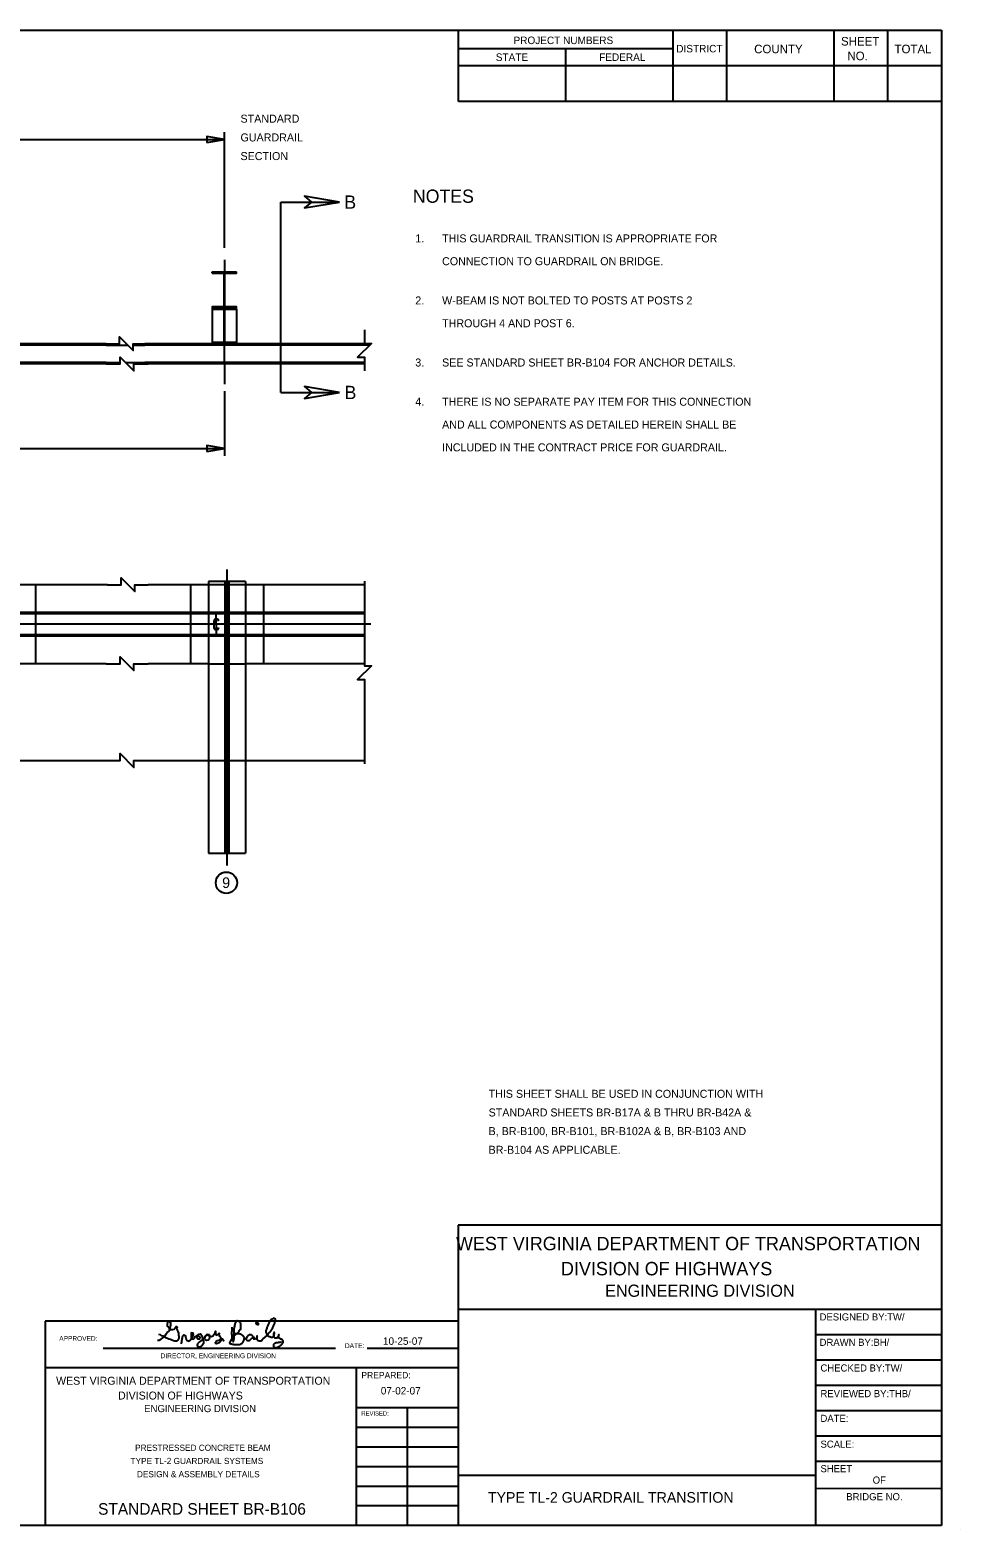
# Model space of a CAD drawing. Extents: x 809.7 to 842.4, y -901 to -880.3.
# Drawn here: x 829.59 to 842.35, y -900.96 to -880.4 of the extents above; entities that cross this region are included whole.
import ezdxf

# ---------------------------------------------------------------- set-up
doc = ezdxf.new("R2010")
doc.units = 0
for name, color, linetype in [('CONSTRUCTION LINE', 7, 'Continuous'), ('CURBLINE', 7, 'Continuous'), ('Default', 7, 'Continuous'), ('DIMENSION LINE', 7, 'Continuous'), ('EDGE OF PAVEMENT', 7, 'Continuous'), ('HIDDEN LINE', 7, 'Continuous'), ('Level 1', 7, 'Continuous'), ('OBJECT LINE', 7, 'Continuous'), ('REBAR', 7, 'Continuous'), ('STRUCTURES CENTERLINE', 7, 'Continuous'), ('STRUCTURES TEXT', 7, 'Continuous'), ('Text', 7, 'Continuous')]:
    doc.layers.add(name, color=color, linetype=linetype)

msp = doc.modelspace()

# ---------------------------------------------------------------- linework, layer by layer
at = {"layer": 'CONSTRUCTION LINE'}
msp.add_line((842.355, -900.957), (842.355, -900.957), dxfattribs=at)
msp.add_line((842.355, -900.957), (842.355, -900.957), dxfattribs=at)
at = {"layer": 'CURBLINE'}
msp.add_line((842.094, -896.791), (835.47, -896.79), dxfattribs=at)
msp.add_line((842.094, -896.791), (835.47, -896.79), dxfattribs=at)
at = {"layer": 'Default'}
for p, q in [((830.598, -898.475), (833.786, -898.475)), ((834.222, -898.475), (835.46, -898.475))]:
    msp.add_line(p, q, dxfattribs=at)
at = {"layer": 'DIMENSION LINE'}
for p, q in [((832.26, -883.385), (832.26, -881.801)), ((826.01, -881.9), (832.26, -881.9)), ((832.26, -885.352), (832.26, -886.236)), ((819.76, -886.137), (832.26, -886.137)), ((832.116, -888.508), (832.116, -888.591))]:
    msp.add_line(p, q, dxfattribs=at)
for centre, start, end in [((832.15, -888.508), 360, 180), ((832.15, -888.591), 180, 0)]:
    msp.add_arc(centre, 0.0339, start, end, dxfattribs=at)
at = {"layer": 'EDGE OF PAVEMENT'}
for points in [[(832.02, -881.94), (832.26, -881.9), (832.02, -881.86)], [(832.02, -886.177), (832.26, -886.137), (832.02, -886.096)]]:
    msp.add_lwpolyline(points, close=True, dxfattribs=at)
msp.add_lwpolyline([(832.26, -886.137), (832.205, -886.137)], dxfattribs=at)
msp.add_circle((832.289, -892.093), 0.146, dxfattribs=at)
at = {"layer": 'HIDDEN LINE'}
for p, q in [((830.637, -884.72), (830.935, -884.72)), ((831.009, -884.72), (831.169, -884.72)), ((832.26, -884.978), (832.26, -884.701)), ((830.637, -884.958), (816.236, -884.958)), ((830.637, -884.957), (830.832, -884.957)), ((830.904, -884.957), (831.169, -884.957)), ((834.183, -884.957), (831.169, -884.957)), ((832.549, -887.964), (832.042, -887.964)), ((832.042, -887.964), (832.042, -890.417)), ((832.549, -887.964), (832.042, -887.964)), ((832.042, -887.964), (832.042, -890.417)), ((832.549, -887.964), (832.042, -887.964)), ((832.042, -887.964), (832.042, -890.417)), ((832.549, -887.964), (832.042, -887.964)), ((832.042, -887.964), (832.042, -890.417)), ((832.549, -887.964), (832.042, -887.964)), ((832.042, -887.964), (832.042, -890.417)), ((832.549, -887.964), (832.042, -887.964)), ((832.042, -887.964), (832.042, -890.417)), ((832.549, -887.964), (832.042, -887.964)), ((832.042, -887.964), (832.042, -890.417)), ((832.549, -887.964), (832.042, -887.964)), ((832.042, -887.964), (832.042, -890.417)), ((832.549, -887.964), (832.042, -887.964)), ((832.042, -887.964), (832.042, -890.417)), ((832.549, -887.964), (832.042, -887.964)), ((832.042, -887.964), (832.042, -890.417)), ((832.549, -887.964), (832.042, -887.964)), ((832.042, -887.964), (832.042, -890.417)), ((832.549, -887.964), (832.042, -887.964)), ((832.042, -887.964), (832.042, -890.417)), ((832.549, -887.964), (832.042, -887.964)), ((832.042, -887.964), (832.042, -890.417)), ((832.549, -887.964), (832.042, -887.964)), ((832.042, -887.964), (832.042, -890.417)), ((832.549, -887.964), (832.042, -887.964)), ((832.042, -887.964), (832.042, -890.417)), ((832.549, -887.964), (832.042, -887.964)), ((832.042, -887.964), (832.042, -890.417)), ((832.269, -887.964), (832.269, -891.69)), ((832.322, -887.964), (832.322, -891.69)), ((832.549, -887.964), (832.549, -890.417)), ((832.549, -887.964), (832.549, -890.417)), ((832.549, -887.964), (832.549, -890.417)), ((832.549, -887.964), (832.549, -890.417)), ((832.549, -887.964), (832.549, -890.417)), ((832.549, -887.964), (832.549, -890.417)), ((832.549, -887.964), (832.549, -890.417)), ((832.549, -887.964), (832.549, -890.417)), ((832.549, -887.964), (832.549, -890.417)), ((832.549, -887.964), (832.549, -890.417)), ((832.549, -887.964), (832.549, -890.417)), ((832.549, -887.964), (832.549, -890.417)), ((832.549, -887.964), (832.549, -890.417)), ((832.549, -887.964), (832.549, -890.417)), ((832.549, -887.964), (832.549, -890.417)), ((832.549, -887.964), (832.549, -890.417)), ((831.796, -888.006), (831.796, -889.089)), ((832.549, -888.006), (832.042, -888.006)), ((834.183, -888.389), (816.316, -888.389)), ((834.183, -888.404), (816.316, -888.404)), ((834.183, -888.694), (816.316, -888.694)), ((834.183, -888.71), (816.316, -888.71)), ((832.042, -889.089), (832.549, -889.089)), ((832.042, -890.417), (832.042, -891.69)), ((832.549, -890.417), (832.549, -891.69)), ((832.042, -891.69), (832.549, -891.69))]:
    msp.add_line(p, q, dxfattribs=at)
at = {"layer": 'Level 1'}
for points in [[(831.341, -898.365), (831.364, -898.369), (831.379, -898.362), (831.4, -898.35), (831.415, -898.334), (831.435, -898.322), (831.453, -898.304), (831.462, -898.281), (831.476, -898.263), (831.494, -898.247), (831.507, -898.228), (831.517, -898.206), (831.521, -898.181), (831.525, -898.157), (831.527, -898.134), (831.513, -898.11), (831.492, -898.11), (831.48, -898.128), (831.476, -898.149), (831.476, -898.173), (831.492, -898.189), (831.505, -898.208), (831.525, -898.22), (831.551, -898.222), (831.572, -898.218), (831.586, -898.2), (831.6, -898.179), (831.611, -898.187), (831.608, -898.208), (831.613, -898.23), (831.621, -898.249), (831.629, -898.269), (831.633, -898.293), (831.637, -898.316), (831.637, -898.34), (831.623, -898.365), (831.608, -898.381), (831.582, -898.381), (831.562, -898.376), (831.539, -898.369), (831.519, -898.357), (831.5, -898.352), (831.478, -898.342), (831.456, -898.334), (831.439, -898.322), (831.419, -898.314), (831.4, -898.306), (831.382, -898.295), (831.362, -898.291)], [(831.669, -898.418), (831.675, -898.396), (831.678, -898.374), (831.681, -898.352), (831.685, -898.331), (831.692, -898.309), (831.705, -898.292), (831.722, -898.304), (831.732, -898.334), (831.736, -898.355), (831.749, -898.371), (831.778, -898.382), (831.794, -898.367), (831.807, -898.35), (831.82, -898.333), (831.827, -898.312), (831.835, -898.292), (831.832, -898.27), (831.803, -898.266), (831.803, -898.288), (831.803, -898.309), (831.806, -898.331), (831.814, -898.351), (831.839, -898.353), (831.852, -898.338), (831.859, -898.316), (831.879, -898.307), (831.9, -898.307), (831.925, -898.326), (831.918, -898.353), (831.897, -898.355), (831.885, -898.338), (831.886, -898.315), (831.893, -898.294), (831.911, -898.284), (831.933, -898.28), (831.951, -898.305), (831.956, -898.327), (831.962, -898.348), (831.969, -898.368), (831.972, -898.39), (831.972, -898.412), (831.956, -898.439), (831.94, -898.453), (831.921, -898.464), (831.899, -898.465), (831.891, -898.436), (831.897, -898.415), (831.91, -898.4), (831.925, -898.388), (831.942, -898.375), (831.968, -898.359), (831.99, -898.337), (831.997, -898.319), (832.012, -898.299), (832.025, -898.283), (832.054, -898.289), (832.058, -898.31), (832.058, -898.332), (832.051, -898.352), (832.034, -898.365), (832.013, -898.372), (831.995, -898.362), (831.991, -898.342), (831.996, -898.321), (832.008, -898.303), (832.028, -898.296), (832.057, -898.308), (832.085, -898.318), (832.11, -898.302), (832.122, -898.286), (832.133, -898.266), (832.141, -898.245), (832.141, -898.255), (832.139, -898.277), (832.148, -898.297), (832.173, -898.29), (832.187, -898.273), (832.189, -898.274), (832.186, -898.296), (832.198, -898.315), (832.214, -898.33), (832.215, -898.351), (832.215, -898.373), (832.203, -898.391), (832.187, -898.405), (832.166, -898.414), (832.146, -898.419), (832.133, -898.403), (832.147, -898.384), (832.165, -898.371), (832.187, -898.367), (832.205, -898.355), (832.235, -898.35), (832.251, -898.374), (832.253, -898.373)], [(832.363, -898.189), (832.364, -898.199), (832.364, -898.21), (832.364, -898.221), (832.364, -898.233), (832.362, -898.244), (832.36, -898.254), (832.36, -898.265), (832.36, -898.276), (832.36, -898.287), (832.361, -898.298), (832.362, -898.308), (832.362, -898.319), (832.363, -898.33), (832.365, -898.341), (832.366, -898.352), (832.367, -898.363), (832.37, -898.374), (832.376, -898.382), (832.382, -898.391), (832.385, -898.38), (832.389, -898.37), (832.392, -898.359), (832.393, -898.349), (832.393, -898.338), (832.393, -898.327), (832.394, -898.316), (832.394, -898.305), (832.395, -898.295), (832.396, -898.284), (832.397, -898.273), (832.397, -898.262), (832.397, -898.251), (832.397, -898.241), (832.397, -898.23), (832.397, -898.219), (832.397, -898.208), (832.398, -898.197), (832.4, -898.187), (832.402, -898.175), (832.405, -898.164), (832.408, -898.153), (832.409, -898.142), (832.413, -898.133), (832.417, -898.123), (832.421, -898.113), (832.426, -898.103), (832.436, -898.099), (832.447, -898.1), (832.458, -898.103), (832.465, -898.111), (832.47, -898.121), (832.476, -898.13), (832.48, -898.14), (832.482, -898.15), (832.483, -898.161), (832.483, -898.172), (832.483, -898.183), (832.483, -898.193), (832.483, -898.204), (832.481, -898.215), (832.476, -898.224), (832.468, -898.231), (832.461, -898.239), (832.457, -898.248), (832.451, -898.257), (832.445, -898.266), (832.441, -898.276), (832.432, -898.282), (832.423, -898.287), (832.414, -898.294), (832.404, -898.299), (832.396, -898.306), (832.388, -898.314), (832.382, -898.323), (832.374, -898.33), (832.369, -898.339), (832.363, -898.348), (832.355, -898.356), (832.349, -898.365), (832.345, -898.375), (832.339, -898.384), (832.335, -898.394), (832.333, -898.404), (832.337, -898.414), (832.347, -898.418), (832.358, -898.419), (832.369, -898.422), (832.379, -898.424), (832.39, -898.425), (832.401, -898.425), (832.413, -898.425), (832.424, -898.425), (832.434, -898.425), (832.445, -898.425), (832.456, -898.425), (832.467, -898.425), (832.477, -898.425), (832.485, -898.417), (832.495, -898.413), (832.504, -898.407), (832.513, -898.4), (832.517, -898.39), (832.521, -898.38), (832.527, -898.371), (832.53, -898.361), (832.533, -898.351), (832.535, -898.34), (832.535, -898.329), (832.529, -898.321), (832.521, -898.314), (832.513, -898.306), (832.506, -898.298), (832.496, -898.292), (832.486, -898.286), (832.476, -898.284), (832.465, -898.282), (832.454, -898.28), (832.442, -898.28), (832.43, -898.28), (832.42, -898.28), (832.409, -898.278), (832.409, -898.278)], [(832.699, -898.132), (832.699, -898.142), (832.707, -898.149), (832.718, -898.152), (832.729, -898.151), (832.731, -898.14), (832.723, -898.134), (832.715, -898.126), (832.704, -898.126), (832.694, -898.13), (832.694, -898.137)], [(832.856, -898.293), (832.862, -898.284), (832.868, -898.275), (832.874, -898.266), (832.881, -898.258), (832.89, -898.252), (832.897, -898.245), (832.902, -898.235), (832.907, -898.225), (832.914, -898.215), (832.92, -898.205), (832.924, -898.195), (832.93, -898.185), (832.935, -898.174), (832.94, -898.163), (832.944, -898.153), (832.948, -898.143), (832.951, -898.134), (832.954, -898.123), (832.958, -898.113), (832.96, -898.102), (832.962, -898.091), (832.96, -898.081), (832.953, -898.073), (832.944, -898.069), (832.933, -898.067), (832.923, -898.073), (832.914, -898.079), (832.904, -898.083), (832.897, -898.089), (832.891, -898.098), (832.885, -898.107), (832.877, -898.115), (832.875, -898.126), (832.871, -898.136), (832.867, -898.145), (832.861, -898.154), (832.857, -898.164), (832.851, -898.173), (832.849, -898.184), (832.844, -898.193), (832.842, -898.203), (832.838, -898.214), (832.834, -898.225), (832.83, -898.235), (832.83, -898.246), (832.83, -898.256), (832.832, -898.267), (832.837, -898.277), (832.841, -898.288), (832.845, -898.298), (832.853, -898.304), (832.863, -898.308), (832.872, -898.315), (832.883, -898.317), (832.893, -898.323), (832.902, -898.327), (832.914, -898.328), (832.925, -898.328), (832.931, -898.319), (832.937, -898.31), (832.942, -898.299), (832.946, -898.289), (832.947, -898.278), (832.95, -898.266), (832.942, -898.259), (832.938, -898.27), (832.934, -898.28), (832.934, -898.291), (832.934, -898.301), (832.934, -898.312), (832.938, -898.323), (832.948, -898.329), (832.957, -898.333), (832.968, -898.334), (832.979, -898.334), (832.989, -898.33), (832.995, -898.32), (833.002, -898.312), (833.006, -898.301), (833.009, -898.291), (833.004, -898.301), (833.001, -898.311), (832.997, -898.321), (833.001, -898.331), (833.01, -898.336), (833.02, -898.341), (833.027, -898.349), (833.038, -898.351), (833.049, -898.355), (833.055, -898.363), (833.059, -898.373), (833.063, -898.383), (833.063, -898.394), (833.061, -898.404), (833.054, -898.411), (833.048, -898.42), (833.04, -898.429), (833.034, -898.438), (833.024, -898.445), (833.016, -898.452), (833.006, -898.457), (832.997, -898.463), (832.988, -898.469), (832.976, -898.47), (832.965, -898.471), (832.954, -898.471), (832.945, -898.465), (832.939, -898.456), (832.937, -898.446), (832.938, -898.435), (832.941, -898.424), (832.947, -898.414), (832.953, -898.406), (832.963, -898.403), (832.973, -898.399), (832.984, -898.397), (832.995, -898.397), (833.005, -898.395), (833.016, -898.395), (833.027, -898.393), (833.038, -898.391), (833.044, -898.389)], [(832.669, -898.364), (832.671, -898.353), (832.671, -898.343), (832.671, -898.332), (832.662, -898.324), (832.654, -898.316), (832.648, -898.307), (832.639, -898.301), (832.631, -898.296), (832.621, -898.292), (832.61, -898.292), (832.599, -898.296), (832.591, -898.302), (832.582, -898.309), (832.575, -898.316), (832.569, -898.325), (832.565, -898.335), (832.559, -898.344), (832.555, -898.353), (832.562, -898.361), (832.569, -898.369), (832.581, -898.372), (832.591, -898.372), (832.602, -898.372), (832.612, -898.368), (832.619, -898.359), (832.626, -898.351), (832.633, -898.343), (832.642, -898.337), (832.654, -898.337), (832.666, -898.338), (832.676, -898.342), (832.686, -898.346), (832.694, -898.351), (832.705, -898.351), (832.708, -898.341), (832.711, -898.33), (832.712, -898.318), (832.712, -898.307), (832.708, -898.317), (832.706, -898.328), (832.706, -898.339), (832.706, -898.35), (832.707, -898.36), (832.717, -898.365), (832.727, -898.371), (832.738, -898.374), (832.748, -898.375), (832.759, -898.375), (832.77, -898.373), (832.779, -898.367), (832.785, -898.357), (832.793, -898.351), (832.798, -898.341), (832.806, -898.334), (832.815, -898.328), (832.823, -898.32), (832.831, -898.312), (832.84, -898.306), (832.848, -898.3), (832.854, -898.293)]]:
    msp.add_lwpolyline(points, dxfattribs=at)
at = {"layer": 'OBJECT LINE'}
for p, q in [((832.092, -883.732), (832.092, -883.716)), ((832.092, -883.716), (832.427, -883.716)), ((832.092, -884.225), (832.092, -884.686)), ((832.427, -884.225), (832.427, -884.686)), ((830.637, -884.701), (816.236, -884.701)), ((830.637, -884.72), (822.502, -884.72)), ((834.274, -884.701), (831.169, -884.701)), ((834.254, -884.72), (831.169, -884.72)), ((832.092, -884.686), (832.092, -884.701)), ((832.427, -884.686), (832.427, -884.701)), ((830.683, -884.978), (816.236, -884.978)), ((834.183, -884.978), (831.169, -884.978)), ((830.657, -888.006), (829.424, -888.006)), ((829.671, -888.006), (829.671, -889.089)), ((832.042, -888.006), (831.215, -888.006)), ((834.183, -888.006), (832.549, -888.006)), ((832.796, -888.006), (832.796, -889.089)), ((830.637, -889.089), (829.424, -889.089)), ((832.042, -889.089), (831.215, -889.089)), ((834.183, -889.089), (832.549, -889.089)), ((816.316, -890.417), (830.637, -890.417)), ((831.215, -890.417), (834.183, -890.417))]:
    msp.add_line(p, q, dxfattribs=at)
for points in [[(832.092, -884.209), (832.427, -884.209), (832.427, -884.194), (832.268, -884.194), (832.268, -883.732)], [(832.252, -883.732), (832.252, -884.194), (832.092, -884.194), (832.092, -884.209)], [(832.092, -883.732), (832.252, -883.732)], [(832.268, -883.732), (832.427, -883.732), (832.427, -883.716)], [(832.092, -884.209), (832.092, -884.225), (832.252, -884.225), (832.252, -884.686)], [(832.268, -884.686), (832.268, -884.225), (832.427, -884.225), (832.427, -884.209)], [(830.637, -884.701), (830.822, -884.701), (830.822, -884.607), (831.009, -884.794), (831.009, -884.701), (831.195, -884.701)], [(830.637, -884.978), (830.832, -884.978), (830.832, -884.885), (831.02, -885.072), (831.02, -884.978), (831.215, -884.978)], [(832.252, -884.686), (832.092, -884.686)], [(832.427, -884.686), (832.268, -884.686)], [(830.657, -888.006), (830.843, -888.006), (830.843, -887.912), (831.03, -888.099), (831.03, -888.006), (831.215, -888.006)], [(834.183, -887.959), (834.183, -889.118), (834.277, -889.118), (834.089, -889.305), (834.183, -889.305), (834.183, -890.464)], [(830.637, -889.089), (830.832, -889.089), (830.832, -888.995), (831.02, -889.183), (831.02, -889.089), (831.215, -889.089)], [(830.637, -890.417), (830.832, -890.417), (830.832, -890.323), (831.02, -890.511), (831.02, -890.417), (831.215, -890.417)]]:
    msp.add_lwpolyline(points, dxfattribs=at)
at = {"layer": 'REBAR'}
for p, q in [((811.186, -880.398), (842.1, -880.399)), ((835.475, -881.38), (835.475, -880.398)), ((838.418, -881.379), (838.419, -880.398)), ((839.154, -881.379), (839.155, -880.398)), ((840.627, -881.379), (840.627, -880.399)), ((841.363, -881.379), (841.364, -880.399)), ((842.1, -880.399), (842.099, -900.909)), ((838.42, -880.656), (835.475, -880.656)), ((836.947, -881.379), (836.947, -880.656)), ((842.099, -880.889), (835.475, -880.888)), ((842.1, -881.379), (835.475, -881.38)), ((835.47, -896.79), (835.47, -900.909)), ((842.094, -896.791), (835.47, -896.79)), ((842.093, -897.946), (835.47, -897.945)), ((840.37, -897.945), (840.37, -900.909)), ((842.093, -897.946), (840.37, -897.945)), ((835.47, -898.105), (829.803, -898.105)), ((829.803, -898.105), (829.803, -900.909)), ((835.47, -898.105), (835.47, -900.909)), ((842.093, -898.293), (840.37, -898.293)), ((842.093, -898.641), (840.37, -898.64)), ((834.068, -898.748), (829.803, -898.748)), ((834.068, -898.748), (834.068, -900.909)), ((835.47, -898.748), (834.068, -898.748)), ((842.093, -898.988), (840.37, -898.988)), ((835.47, -899.297), (834.068, -899.297)), ((834.769, -899.297), (834.769, -900.909)), ((842.093, -899.336), (840.37, -899.335)), ((835.47, -899.566), (834.068, -899.566)), ((835.47, -899.493), (835.47, -900.909)), ((842.093, -899.683), (840.37, -899.683)), ((835.47, -899.834), (834.068, -899.834)), ((835.47, -900.103), (834.068, -900.103)), ((842.093, -900.031), (840.37, -900.03)), ((840.37, -900.221), (835.47, -900.221)), ((835.47, -900.374), (834.068, -900.374)), ((842.094, -900.404), (840.377, -900.403)), ((835.47, -900.641), (834.068, -900.641)), ((842.099, -900.909), (811.184, -900.908))]:
    msp.add_line(p, q, dxfattribs=at)
at = {"layer": 'STRUCTURES CENTERLINE'}
for p, q in [((833.036, -882.758), (833.842, -882.758)), ((833.036, -885.369), (833.036, -882.758)), ((832.26, -883.549), (832.26, -884.701)), ((832.26, -884.978), (832.26, -885.253)), ((833.036, -885.369), (833.842, -885.369)), ((832.296, -887.797), (832.296, -891.857)), ((834.271, -888.549), (816.316, -888.549)), ((832.15, -888.549), (832.15, -888.385)), ((832.15, -888.549), (832.15, -888.713))]:
    msp.add_line(p, q, dxfattribs=at)
for points in [[(833.842, -882.758), (833.359, -882.677), (833.456, -882.758), (833.359, -882.839)], [(833.842, -885.369), (833.359, -885.289), (833.456, -885.369), (833.359, -885.45)]]:
    msp.add_lwpolyline(points, close=True, dxfattribs=at)
msp.add_lwpolyline([(834.183, -884.511), (834.183, -884.698), (834.277, -884.698), (834.089, -884.885), (834.183, -884.885), (834.183, -885.072)], dxfattribs=at)

# ---------------------------------------------------------------- texts
at = {"layer": 'OBJECT LINE'}
for s, height, p in [('PROJECT NUMBERS', 0.10288, (836.228, -880.591)), ('SHEET', 0.1177, (840.722, -880.611)), ('STATE', 0.1029, (835.985, -880.822)), ('FEDERAL', 0.1029, (837.403, -880.822)), ('DISTRICT', 0.1029, (838.461, -880.705)), ('  NO.', 0.1177, (840.722, -880.812)), ('TOTAL', 0.1177, (841.456, -880.717))]:
    msp.add_text(s, height=height, dxfattribs=at).set_placement(p)
at = {"layer": 'STRUCTURES TEXT'}
for s, height, p in [('STANDARD', 0.1098, (832.482, -881.669)), ('GUARDRAIL', 0.1098, (832.482, -881.926)), ('SECTION', 0.1098, (832.482, -882.182)), ('NOTES', 0.1818, (834.847, -882.768)), ('B', 0.182, (833.906, -882.849)), ('1.', 0.1098, (834.88, -883.311)), ('THIS GUARDRAIL TRANSITION IS APPROPRIATE FOR', 0.10979, (835.248, -883.311)), ('CONNECTION TO GUARDRAIL ON BRIDGE.', 0.10979, (835.248, -883.624)), ('2.', 0.1098, (834.88, -884.162)), ('W-BEAM IS NOT BOLTED TO POSTS AT POSTS 2', 0.10979, (835.248, -884.162)), ('THROUGH 4 AND POST 6.', 0.10979, (835.248, -884.475)), ('3.', 0.1098, (834.88, -885.013)), ('SEE STANDARD SHEET BR-B104 FOR ANCHOR DETAILS.', 0.10979, (835.248, -885.013)), ('B', 0.182, (833.909, -885.46)), ('4.', 0.1098, (834.88, -885.551)), ('THERE IS NO SEPARATE PAY ITEM FOR THIS CONNECTION', 0.10979, (835.248, -885.551)), ('AND ALL COMPONENTS AS DETAILED HEREIN SHALL BE', 0.10979, (835.248, -885.864)), ('INCLUDED IN THE CONTRACT PRICE FOR GUARDRAIL.', 0.10979, (835.248, -886.177)), ('9', 0.146, (832.23, -892.166)), ('THIS SHEET SHALL BE USED IN CONJUNCTION WITH ', 0.10979, (835.886, -895.043)), ('STANDARD SHEETS BR-B17A & B THRU BR-B42A & ', 0.10979, (835.886, -895.299)), ('B, BR-B100, BR-B101, BR-B102A & B, BR-B103 AND ', 0.10979, (835.886, -895.555)), ('BR-B104 AS APPLICABLE.', 0.10979, (835.886, -895.811)), ('APPROVED:                                                  ', 0.06507, (829.995, -898.376)), ('DATE:', 0.0657, (833.914, -898.475)), ('10-25-07', 0.1022, (834.437, -898.431)), ('DIRECTOR, ENGINEERING DIVISION', 0.06573, (831.385, -898.614)), ('PREPARED:', 0.0876, (834.14, -898.891)), ('07-02-07', 0.1022, (834.407, -899.112)), ('REVISED:', 0.0584, (834.14, -899.401)), ('PRESTRESSED CONCRETE BEAM', 0.08454, (831.036, -899.885)), ('TYPE TL-2 GUARDRAIL SYSTEMS', 0.08454, (830.973, -900.066)), ('DESIGN & ASSEMBLY DETAILS', 0.08454, (831.061, -900.247))]:
    msp.add_text(s, height=height, dxfattribs=at).set_placement(p)
for s, height, p in [(' WEST VIRGINIA DEPARTMENT OF TRANSPORTATION', 0.18406, (835.371, -897.134)), ('    DIVISION OF HIGHWAYS', 0.18406, (836.606, -897.478)), ('ENGINEERING DIVISION', 0.16673, (837.484, -897.772)), ('DESIGNED BY:TW/', 0.09746, (840.428, -898.097)), ('DRAWN BY:BH/', 0.09746, (840.428, -898.445)), (' WEST VIRGINIA DEPARTMENT OF TRANSPORTATION', 0.10869, (829.911, -898.978)), ('CHECKED BY:TW/', 0.09746, (840.44, -898.797)), ('    DIVISION OF HIGHWAYS', 0.10869, (830.64, -899.181)), ('REVIEWED BY:THB/', 0.09746, (840.44, -899.149)), ('ENGINEERING DIVISION', 0.09845, (831.159, -899.354)), ('DATE:', 0.0975, (840.44, -899.488)), ('SCALE:', 0.0975, (840.44, -899.842)), ('SHEET', 0.0975, (840.44, -900.178)), ('TYPE TL-2 GUARDRAIL TRANSITION', 0.14492, (835.877, -900.596)), ('STANDARD SHEET BR-B106', 0.15855, (830.528, -900.761))]:
    msp.add_text(s, height=height, rotation=359.9983, dxfattribs=at).set_placement(p)
at = {"layer": 'Text'}
for s, height, p in [('COUNTY', 0.1177, (839.53, -880.717)), ('OF', 0.0983, (841.156, -900.335)), ('BRIDGE NO.', 0.0983, (840.793, -900.563))]:
    msp.add_text(s, height=height, rotation=359.9983, dxfattribs=at).set_placement(p)

doc.saveas('drawing.dxf')
